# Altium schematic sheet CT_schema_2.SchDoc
size 176 x 147 mm
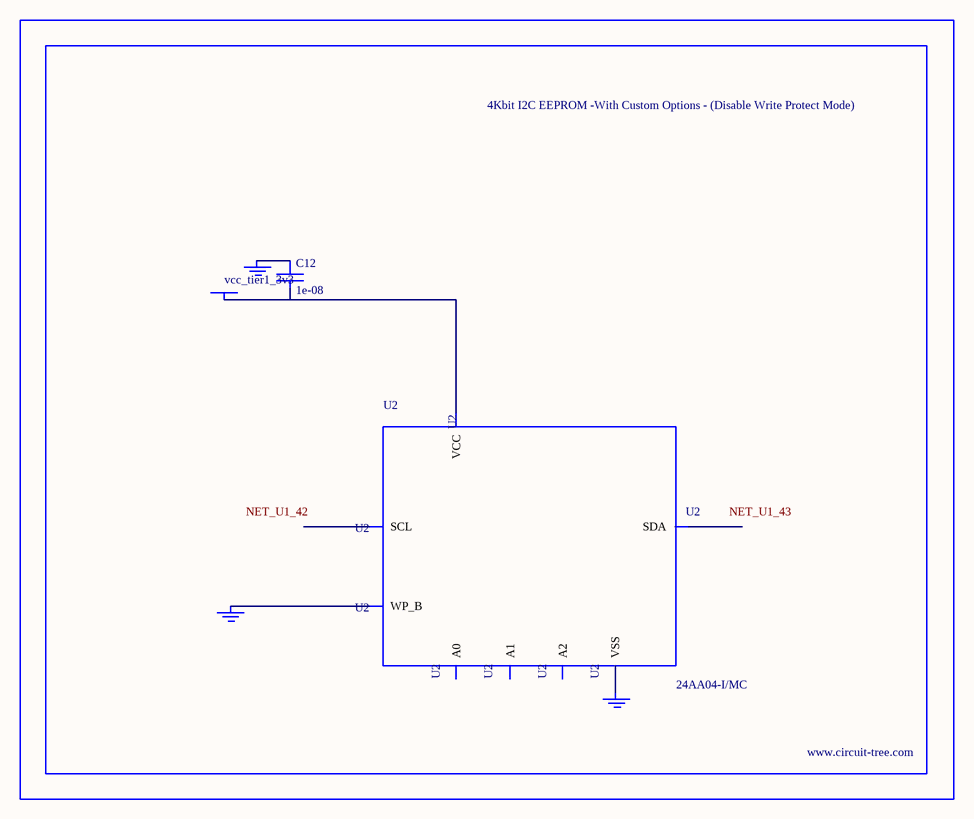
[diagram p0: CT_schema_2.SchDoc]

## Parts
BORDER1  (no value)
C12  1e-08  [C0402]
GND_INSTANCE_1_0  (no value)
GND_INSTANCE_1_1  (no value)
GND_INSTANCE_1_2  (no value)
POWER_INSTANCE_1_0  vcc_tier1_3v3
U2  24AA04-I/MC  [TDFN-8/6MM]

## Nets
NetC12_1: C12.1 GND_INSTANCE_1_1.0(GND)
NetC12_2: C12.2 POWER_INSTANCE_1_0.0(PWR) U2.8(VCC)
NetGND_INSTANCE_1_0_0: GND_INSTANCE_1_0.0(GND) U2.7(WP_B)
NetGND_INSTANCE_1_2_0: GND_INSTANCE_1_2.0(GND) U2.4(VSS)

Not connected (* = marked no-connect by the designer): U2 1(A0) 2(A1) 3(A2) 5(SDA) 6(SCL)

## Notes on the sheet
- Labels drawn without touching a wire or pin: NET_U1_42, NET_U1_43

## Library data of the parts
BORDER1 = BORDER_PAGE1
C12 = C0402C103K3RAC
GND_INSTANCE_1_0-GND_INSTANCE_1_2 = GND
POWER_INSTANCE_1_0 = PWR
